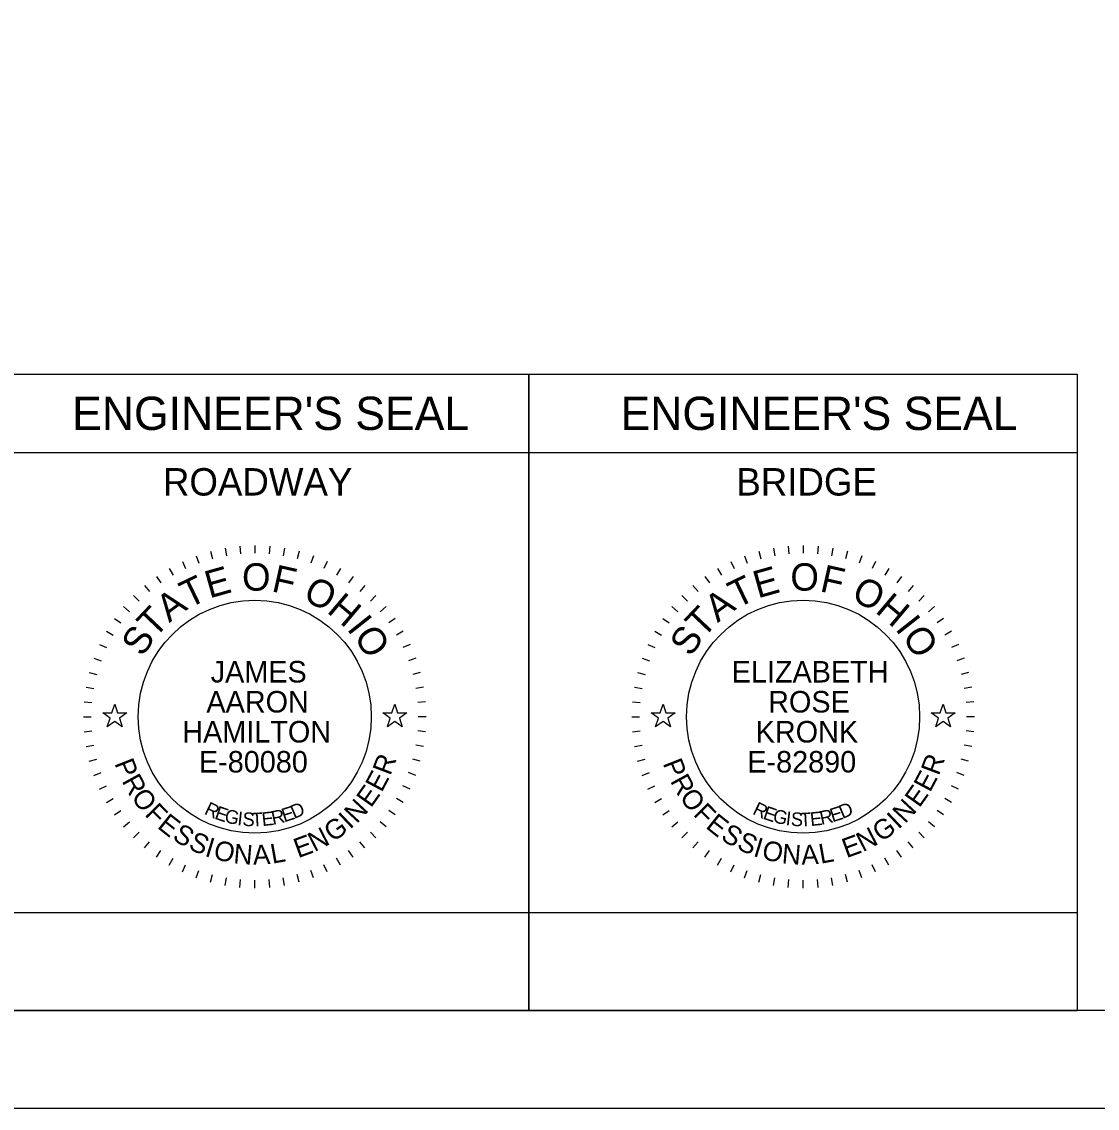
# Model space of a CAD drawing. Extents: x 0 to 34, y 0 to 22.
# Drawn here: x 23.81 to 29.3, y 0 to 5.55 of the extents above; entities that cross this region are included whole.
import ezdxf

# ---------------------------------------------------------------- set-up
doc = ezdxf.new("R2010")
doc.units = 0
for name, color, linetype in [('Default', 7, 'Continuous'), ('GM_X_County', 7, 'Continuous'), ('GM_X_Minor_Lake_Text', 7, 'Continuous'), ('GM_X_Minor_River_Text', 7, 'Continuous')]:
    doc.layers.add(name, color=color, linetype=linetype)

msp = doc.modelspace()

# ---------------------------------------------------------------- linework, layer by layer
at = {"layer": 'Default'}
for points in [[(24.2236, 2.02), (24.2705, 2.02), (24.285, 2.0645), (24.2995, 2.02), (24.3464, 2.02), (24.3085, 1.9924), (24.323, 1.9478), (24.285, 1.9754), (24.247, 1.9478), (24.2615, 1.9924)], [(25.6536, 2.02), (25.7005, 2.02), (25.715, 2.0645), (25.7295, 2.02), (25.7764, 2.02), (25.7385, 1.9924), (25.753, 1.9478), (25.715, 1.9754), (25.677, 1.9478), (25.6915, 1.9924)], [(27.0236, 2.02), (27.0705, 2.02), (27.085, 2.0645), (27.0995, 2.02), (27.1464, 2.02), (27.1085, 1.9924), (27.123, 1.9478), (27.085, 1.9754), (27.047, 1.9478), (27.0615, 1.9924)], [(28.4536, 2.02), (28.5005, 2.02), (28.515, 2.0645), (28.5295, 2.02), (28.5764, 2.02), (28.5385, 1.9924), (28.553, 1.9478), (28.515, 1.9754), (28.477, 1.9478), (28.4915, 1.9924)]]:
    msp.add_lwpolyline(points, close=True, dxfattribs=at)
at = {"layer": 'GM_X_County'}
msp.add_lwpolyline([(0, 0), (34, 0), (34, 22), (0, 22)], close=True, dxfattribs=at)
at = {"layer": 'GM_X_Minor_Lake_Text'}
for p, q in [((23.6, 3.75), (26.4, 3.75)), ((26.4, 3.75), (26.4, 0.5)), ((26.4, 0.5), (26.4, 3.75)), ((26.4, 3.75), (29.2, 3.75)), ((29.2, 3.75), (29.2, 0.5)), ((23.6, 3.35), (26.4, 3.35)), ((26.4, 3.35), (29.2, 3.35)), ((24.7735, 2.8452), (24.7839, 2.8065)), ((24.8481, 2.8617), (24.855, 2.8223)), ((24.9237, 2.8717), (24.9272, 2.8318)), ((25, 2.875), (25, 2.835)), ((25.0763, 2.8717), (25.0728, 2.8318)), ((25.1519, 2.8617), (25.145, 2.8223)), ((25.2265, 2.8452), (25.2161, 2.8065)), ((27.5735, 2.8452), (27.5839, 2.8065)), ((27.6481, 2.8617), (27.655, 2.8223)), ((27.7237, 2.8717), (27.7272, 2.8318)), ((27.8, 2.875), (27.8, 2.835)), ((27.8763, 2.8717), (27.8728, 2.8318)), ((27.9519, 2.8617), (27.945, 2.8223)), ((28.0265, 2.8452), (28.0161, 2.8065)), ((24.6302, 2.793), (24.6471, 2.7568)), ((24.7007, 2.8222), (24.7144, 2.7846)), ((25.2993, 2.8222), (25.2856, 2.7846)), ((25.3698, 2.793), (25.3529, 2.7568)), ((27.4302, 2.793), (27.4471, 2.7568)), ((27.5007, 2.8222), (27.5144, 2.7846)), ((28.0993, 2.8222), (28.0856, 2.7846)), ((28.1698, 2.793), (28.1529, 2.7568)), ((24.5625, 2.7578), (24.5825, 2.7231)), ((25.4375, 2.7578), (25.4175, 2.7231)), ((27.3625, 2.7578), (27.3825, 2.7231)), ((28.2375, 2.7578), (28.2175, 2.7231)), ((24.4376, 2.6703), (24.4633, 2.6396)), ((24.4981, 2.7168), (24.5211, 2.684)), ((25.5019, 2.7168), (25.4789, 2.684)), ((25.5624, 2.6703), (25.5367, 2.6396)), ((27.2376, 2.6703), (27.2633, 2.6396)), ((27.2981, 2.7168), (27.3211, 2.684)), ((28.3019, 2.7168), (28.2789, 2.684)), ((28.3624, 2.6703), (28.3367, 2.6396)), ((24.3813, 2.6187), (24.4096, 2.5904)), ((25.6187, 2.6187), (25.5904, 2.5904)), ((27.1813, 2.6187), (27.2096, 2.5904)), ((28.4187, 2.6187), (28.3904, 2.5904)), ((24.3297, 2.5624), (24.3604, 2.5367)), ((25.6703, 2.5624), (25.6396, 2.5367)), ((27.1297, 2.5624), (27.1604, 2.5367)), ((28.4703, 2.5624), (28.4396, 2.5367)), ((24.2832, 2.5019), (24.316, 2.4789)), ((25.7168, 2.5019), (25.684, 2.4789)), ((27.0832, 2.5019), (27.116, 2.4789)), ((28.5168, 2.5019), (28.484, 2.4789)), ((24.2422, 2.4375), (24.2769, 2.4175)), ((25.7578, 2.4375), (25.7231, 2.4175)), ((27.0422, 2.4375), (27.0769, 2.4175)), ((28.5578, 2.4375), (28.5231, 2.4175)), ((24.207, 2.3698), (24.2432, 2.3529)), ((25.793, 2.3698), (25.7568, 2.3529)), ((27.007, 2.3698), (27.0432, 2.3529)), ((28.593, 2.3698), (28.5568, 2.3529)), ((24.1778, 2.2993), (24.2154, 2.2856)), ((25.8222, 2.2993), (25.7846, 2.2856)), ((26.9778, 2.2993), (27.0154, 2.2856)), ((28.6222, 2.2993), (28.5846, 2.2856)), ((24.1548, 2.2265), (24.1935, 2.2161)), ((25.8452, 2.2265), (25.8065, 2.2161)), ((26.9548, 2.2265), (26.9935, 2.2161)), ((28.6452, 2.2265), (28.6065, 2.2161)), ((24.1383, 2.1519), (24.1777, 2.145)), ((25.8617, 2.1519), (25.8223, 2.145)), ((26.9383, 2.1519), (26.9777, 2.145)), ((28.6617, 2.1519), (28.6223, 2.145)), ((24.1283, 2.0763), (24.1682, 2.0728)), ((25.8717, 2.0763), (25.8318, 2.0728)), ((26.9283, 2.0763), (26.9682, 2.0728)), ((28.6717, 2.0763), (28.6318, 2.0728)), ((24.125, 2), (24.165, 2)), ((25.875, 2), (25.835, 2)), ((26.925, 2), (26.965, 2)), ((28.675, 2), (28.635, 2)), ((24.1283, 1.9237), (24.1682, 1.9272)), ((25.8717, 1.9237), (25.8318, 1.9272)), ((26.9283, 1.9237), (26.9682, 1.9272)), ((28.6717, 1.9237), (28.6318, 1.9272)), ((24.1383, 1.8481), (24.1777, 1.855)), ((25.8617, 1.8481), (25.8223, 1.855)), ((26.9383, 1.8481), (26.9777, 1.855)), ((28.6617, 1.8481), (28.6223, 1.855)), ((24.1548, 1.7735), (24.1935, 1.7839)), ((25.8452, 1.7735), (25.8065, 1.7839)), ((26.9548, 1.7735), (26.9935, 1.7839)), ((28.6452, 1.7735), (28.6065, 1.7839)), ((24.1778, 1.7007), (24.2154, 1.7144)), ((25.8222, 1.7007), (25.7846, 1.7144)), ((26.9778, 1.7007), (27.0154, 1.7144)), ((28.6222, 1.7007), (28.5846, 1.7144)), ((24.207, 1.6302), (24.2432, 1.6471)), ((25.793, 1.6302), (25.7568, 1.6471)), ((27.007, 1.6302), (27.0432, 1.6471)), ((28.593, 1.6302), (28.5568, 1.6471)), ((24.2422, 1.5625), (24.2769, 1.5825)), ((25.7578, 1.5625), (25.7231, 1.5825)), ((27.0422, 1.5625), (27.0769, 1.5825)), ((28.5578, 1.5625), (28.5231, 1.5825)), ((24.2832, 1.4981), (24.316, 1.5211)), ((25.7168, 1.4981), (25.684, 1.5211)), ((27.0832, 1.4981), (27.116, 1.5211)), ((28.5168, 1.4981), (28.484, 1.5211)), ((24.3297, 1.4376), (24.3604, 1.4633)), ((25.6703, 1.4376), (25.6396, 1.4633)), ((27.1297, 1.4376), (27.1604, 1.4633)), ((28.4703, 1.4376), (28.4396, 1.4633)), ((24.3813, 1.3813), (24.4096, 1.4096)), ((25.6187, 1.3813), (25.5904, 1.4096)), ((27.1813, 1.3813), (27.2096, 1.4096)), ((28.4187, 1.3813), (28.3904, 1.4096)), ((24.4376, 1.3297), (24.4633, 1.3604)), ((25.5624, 1.3297), (25.5367, 1.3604)), ((27.2376, 1.3297), (27.2633, 1.3604)), ((28.3624, 1.3297), (28.3367, 1.3604)), ((24.4981, 1.2832), (24.5211, 1.316)), ((24.5625, 1.2422), (24.5825, 1.2769)), ((25.4375, 1.2422), (25.4175, 1.2769)), ((25.5019, 1.2832), (25.4789, 1.316)), ((27.2981, 1.2832), (27.3211, 1.316)), ((27.3625, 1.2422), (27.3825, 1.2769)), ((28.2375, 1.2422), (28.2175, 1.2769)), ((28.3019, 1.2832), (28.2789, 1.316)), ((24.6302, 1.207), (24.6471, 1.2432)), ((25.3698, 1.207), (25.3529, 1.2432)), ((27.4302, 1.207), (27.4471, 1.2432)), ((28.1698, 1.207), (28.1529, 1.2432)), ((24.7007, 1.1778), (24.7144, 1.2154)), ((24.7735, 1.1548), (24.7839, 1.1935)), ((24.8481, 1.1383), (24.855, 1.1777)), ((24.9237, 1.1283), (24.9272, 1.1682)), ((25.0763, 1.1283), (25.0728, 1.1682)), ((25.1519, 1.1383), (25.145, 1.1777)), ((25.2265, 1.1548), (25.2161, 1.1935)), ((25.2993, 1.1778), (25.2856, 1.2154)), ((27.5007, 1.1778), (27.5144, 1.2154)), ((27.5735, 1.1548), (27.5839, 1.1935)), ((27.6481, 1.1383), (27.655, 1.1777)), ((27.7237, 1.1283), (27.7272, 1.1682)), ((27.8763, 1.1283), (27.8728, 1.1682)), ((27.9519, 1.1383), (27.945, 1.1777)), ((28.0265, 1.1548), (28.0161, 1.1935)), ((28.0993, 1.1778), (28.0856, 1.2154)), ((25, 1.125), (25, 1.165)), ((27.8, 1.125), (27.8, 1.165)), ((23.6, 0.5), (26.4, 0.5)), ((26.4, 0.5), (29.2, 0.5))]:
    msp.add_line(p, q, dxfattribs=at)
for points in [[(23.6, 0.5), (23.6, 1), (26.4, 1), (26.4, 0.5)], [(26.4, 0.5), (26.4, 1), (29.2, 1), (29.2, 0.5)]]:
    msp.add_lwpolyline(points, close=True, dxfattribs=at)
for centre in [(25, 2), (27.8, 2)]:
    msp.add_circle(centre, 0.595, dxfattribs=at)
at = {"layer": 'GM_X_Minor_River_Text'}
msp.add_lwpolyline([(1.5, 21.5), (33.5, 21.5), (33.5, 0.5), (1.5, 0.5)], close=True, dxfattribs=at)

# ---------------------------------------------------------------- texts
at = {"layer": 'GM_X_Minor_Lake_Text'}
for s, height, p in [("ENGINEER'S SEAL", 0.17, (24.0676, 3.465)), ("ENGINEER'S SEAL", 0.17, (26.8676, 3.465)), ('ROADWAY', 0.14, (24.5311, 3.13)), ('BRIDGE', 0.14, (27.459, 3.13)), ('JAMES', 0.11, (24.775, 2.1749)), ('ELIZABETH', 0.11, (27.4353, 2.1749)), ('AARON', 0.11, (24.753, 2.0216)), ('ROSE', 0.11, (27.6214, 2.0216)), ('HAMILTON', 0.11, (24.6298, 1.8684)), ('KRONK', 0.11, (27.5576, 1.8684)), ('E-80080', 0.11, (24.7149, 1.7151)), ('E-82890', 0.11, (27.5149, 1.7151))]:
    msp.add_text(s, height=height, dxfattribs=at).set_placement(p)
for s, height, rotation, p in [('O', 0.14, 359.7812, (24.9347, 2.6443)), ('O', 0.14, 359.7812, (27.7347, 2.6443)), ('T', 0.14, 25.7167, (24.6616, 2.5518)), ('E', 0.14, 15.7571, (24.7684, 2.6038)), ('F', 0.14, 347.4362, (25.0811, 2.6417)), ('T', 0.14, 25.7167, (27.4616, 2.5518)), ('E', 0.14, 15.7571, (27.5684, 2.6038)), ('F', 0.14, 347.4362, (27.8811, 2.6417)), ('O', 0.14, 332.2586, (25.2398, 2.6015)), ('O', 0.14, 332.2586, (28.0398, 2.6015)), ('A', 0.14, 36.4747, (24.5634, 2.4781)), ('H', 0.14, 319.9136, (25.3632, 2.5361)), ('A', 0.14, 36.4747, (27.3634, 2.4781)), ('H', 0.14, 319.9136, (28.1632, 2.5361)), ('T', 0.14, 46.4344, (24.4883, 2.3964)), ('T', 0.14, 46.4344, (27.2883, 2.3964)), ('I', 0.14, 308.367, (25.4665, 2.4483)), ('I', 0.14, 308.367, (28.2665, 2.4483)), ('S', 0.14, 57.1924, (24.4281, 2.3014)), ('O', 0.14, 303.1491, (25.5021, 2.4089)), ('S', 0.14, 57.1924, (27.2281, 2.3014)), ('O', 0.14, 303.1491, (28.3021, 2.4089)), ('P', 0.1, 291.494, (24.2823, 1.7621)), ('R', 0.1, 69.2322, (25.6919, 1.6954)), ('P', 0.1, 291.494, (27.0823, 1.7621)), ('R', 0.1, 69.2322, (28.4919, 1.6954)), ('E', 0.1, 61.9951, (25.6476, 1.6098)), ('E', 0.1, 61.9951, (28.4476, 1.6098)), ('R', 0.1, 298.7311, (24.319, 1.6717)), ('R', 0.1, 298.7311, (27.119, 1.6717)), ('O', 0.1, 306.4666, (24.3655, 1.5883)), ('E', 0.1, 54.758, (25.5933, 1.5314)), ('O', 0.1, 306.4666, (27.1655, 1.5883)), ('E', 0.1, 54.758, (28.3933, 1.5314)), ('F', 0.1, 314.7068, (24.4343, 1.4983)), ('R', 0.07, 334.487, (24.7375, 1.5051)), ('D', 0.07, 23.3052, (25.201, 1.477)), ('N', 0.1, 47.0224, (25.5202, 1.4508)), ('F', 0.1, 314.7068, (27.2343, 1.4983)), ('R', 0.07, 334.487, (27.5375, 1.5051)), ('D', 0.07, 23.3052, (28.001, 1.477)), ('N', 0.1, 47.0224, (28.3202, 1.4508)), ('E', 0.1, 321.4393, (24.4978, 1.4348)), ('E', 0.07, 341.04, (24.7906, 1.4801)), ('G', 0.07, 347.4752, (24.8414, 1.4618)), ('I', 0.07, 353.7858, (24.9091, 1.4468)), ('S', 0.07, 356.8926, (24.9358, 1.4429)), ('T', 0.07, 3.0061, (24.9857, 1.4387)), ('E', 0.07, 6.0117, (25.0389, 1.4412)), ('R', 0.07, 11.9184, (25.0925, 1.4474)), ('E', 0.07, 17.6836, (25.1498, 1.4602)), ('I', 0.1, 43.287, (25.4868, 1.4214)), ('E', 0.1, 321.4393, (27.2978, 1.4348)), ('E', 0.07, 341.04, (27.5906, 1.4801)), ('G', 0.07, 347.4752, (27.6414, 1.4618)), ('I', 0.07, 353.7858, (27.7091, 1.4468)), ('S', 0.07, 356.8926, (27.7358, 1.4429)), ('T', 0.07, 3.0061, (27.7857, 1.4387)), ('E', 0.07, 6.0117, (27.8389, 1.4412)), ('R', 0.07, 11.9184, (27.8925, 1.4474)), ('E', 0.07, 17.6836, (27.9498, 1.4602)), ('I', 0.1, 43.287, (28.2868, 1.4214)), ('S', 0.1, 328.6764, (24.5743, 1.3752)), ('G', 0.1, 35.0469, (25.3981, 1.357)), ('S', 0.1, 328.6764, (27.3743, 1.3752)), ('G', 0.1, 35.0469, (28.1981, 1.357)), ('S', 0.1, 335.9134, (24.6564, 1.3266)), ('E', 0.1, 20.0742, (25.2212, 1.277)), ('N', 0.1, 27.3113, (25.3045, 1.3075)), ('S', 0.1, 335.9134, (27.4564, 1.3266)), ('E', 0.1, 20.0742, (28.0212, 1.277)), ('N', 0.1, 27.3113, (28.1045, 1.3075)), ('I', 0.1, 343.1505, (24.7406, 1.2897)), ('O', 0.1, 346.8859, (24.7839, 1.2751)), ('N', 0.1, 355.1261, (24.8888, 1.2517)), ('A', 0.1, 2.8617, (24.9923, 1.2437)), ('L', 0.1, 10.0987, (25.0894, 1.249)), ('I', 0.1, 343.1505, (27.5406, 1.2897)), ('O', 0.1, 346.8859, (27.5839, 1.2751)), ('N', 0.1, 355.1261, (27.6888, 1.2517)), ('A', 0.1, 2.8617, (27.7923, 1.2437)), ('L', 0.1, 10.0987, (27.8894, 1.249))]:
    msp.add_text(s, height=height, rotation=rotation, dxfattribs=at).set_placement(p)

doc.saveas('drawing.dxf')
